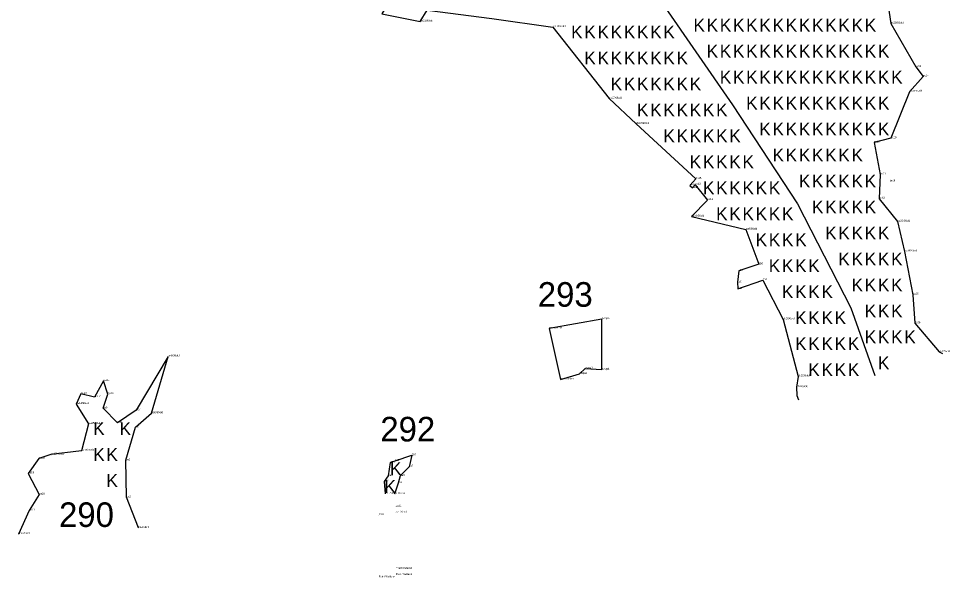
# Model space of a CAD drawing. Extents: x 2072529 to 2268812, y 436423 to 470008.
# Drawn here: x 2250300 to 2252772, y 437368 to 438853 of the extents above; entities that cross this region are included whole.
import ezdxf

# ---------------------------------------------------------------- set-up
doc = ezdxf.new("R2010")
doc.units = 0
for name, color, linetype in [('Old_Level_10', 7, 'Continuous'), ('Old_Level_20', 7, 'Continuous'), ('Old_Level_52', 7, 'Continuous'), ('Old_Level_55', 7, 'Continuous'), ('Old_Level_60', 7, 'Continuous'), ('Old_Level_62', 7, 'Continuous')]:
    doc.layers.add(name, color=color, linetype=linetype)

msp = doc.modelspace()

# ---------------------------------------------------------------- linework, layer by layer
at = {"layer": 'Old_Level_10'}
for p, q in [((2252009.775, 438893.449), (2252195.923, 438623.668)), ((2252195.923, 438623.668), (2252369.234, 438360.311)), ((2252369.234, 438360.311), (2252510.449, 438084.108)), ((2252510.449, 438084.108), (2252574.638, 437904.254))]:
    msp.add_line(p, q, dxfattribs=at)
msp.add_lwpolyline([(2251739.019, 437894.057), (2251789.687, 437908.798), (2251805.058, 437923.355), (2251849.076, 437920.135), (2251849.191, 438054.202), (2251709.629, 438029.479), (2251739.019, 437894.057)], dxfattribs=at)
at = {"layer": 'Old_Level_20'}
for p, q in [((2251366.822, 438844.78), (2251366.822, 438844.78)), ((2252617.059, 438839.416), (2252617.059, 438839.416)), ((2251718.819, 438830.133), (2251718.819, 438830.133)), ((2252682.756, 438724.15), (2252682.756, 438724.15)), ((2252702.337, 438698.781), (2252702.337, 438698.781)), ((2251868.445, 438639.973), (2251868.445, 438639.973)), ((2252666.604, 438658.157), (2252666.604, 438658.157)), ((2251940.741, 438572.887), (2251940.741, 438572.887)), ((2252572.116, 438523.425), (2252572.116, 438523.425)), ((2252617.067, 438534.575), (2252617.067, 438534.575)), ((2252098.489, 438426.718), (2252098.489, 438426.718)), ((2252588.626, 438438.611), (2252588.626, 438438.611)), ((2252614.962, 438420.413), (2252614.962, 438420.413)), ((2252083.026, 438409.31), (2252083.026, 438409.31)), ((2252090.254, 438402.804), (2252090.254, 438402.804)), ((2252096.843, 438411.378), (2252096.843, 438411.378)), ((2252129.608, 438370.679), (2252129.608, 438370.679)), ((2252585.902, 438374.204), (2252585.902, 438374.204)), ((2252087.239, 438326.638), (2252087.239, 438326.638)), ((2252231.674, 438292.269), (2252231.674, 438292.269)), ((2252634.629, 438313.221), (2252634.629, 438313.221)), ((2252652.916, 438234.163), (2252652.916, 438234.163)), ((2252265.763, 438199.96), (2252265.763, 438199.96)), ((2252213.023, 438182.133), (2252213.023, 438182.133)), ((2252209.119, 438152.048), (2252209.119, 438152.048)), ((2252276.43, 438157.855), (2252276.43, 438157.855)), ((2252210.196, 438134.316), (2252210.196, 438134.316)), ((2252675.403, 438119.227), (2252675.403, 438119.227)), ((2251849.191, 438054.202), (2251849.191, 438054.202)), ((2252330.724, 438053.701), (2252330.724, 438053.701)), ((2252680.549, 438043.335), (2252680.549, 438043.335)), ((2251709.629, 438029.479), (2251709.629, 438029.479)), ((2250696.964, 437955.41), (2250696.964, 437955.41)), ((2252745.583, 437967.012), (2252745.583, 437967.012)), ((2251805.058, 437923.355), (2251805.058, 437923.355)), ((2251849.076, 437920.135), (2251849.076, 437920.135)), ((2251789.687, 437908.798), (2251789.687, 437908.798)), ((2252370.675, 437902.256), (2252370.675, 437902.256)), ((2250525.719, 437889.973), (2250525.719, 437889.973)), ((2251739.019, 437894.057), (2251739.019, 437894.057)), ((2252366.636, 437873.552), (2252366.636, 437873.552)), ((2250465.038, 437855.514), (2250465.038, 437855.514)), ((2250501.969, 437847.269), (2250501.969, 437847.269)), ((2250537.012, 437854.96), (2250537.012, 437854.96)), ((2250452.829, 437828.757), (2250452.829, 437828.757)), ((2250524.177, 437817.337), (2250524.177, 437817.337)), ((2250611.988, 437812.401), (2250611.988, 437812.401)), ((2250653.197, 437804.291), (2250653.197, 437804.291)), ((2250485.912, 437775.713), (2250485.912, 437775.713)), ((2250562.617, 437779.2), (2250562.617, 437779.2)), ((2250610.143, 437767.229), (2250610.143, 437767.229)), ((2250466.867, 437704.451), (2250466.867, 437704.451)), ((2250354.116, 437683.813), (2250354.116, 437683.813)), ((2250385.955, 437694.223), (2250385.955, 437694.223)), ((2250585.02, 437679.174), (2250585.02, 437679.174)), ((2251287.405, 437673.349), (2251287.405, 437673.349)), ((2251299.79, 437677.728), (2251299.79, 437677.728)), ((2251344.17, 437692.721), (2251344.17, 437692.721)), ((2251336.971, 437662.251), (2251336.971, 437662.251)), ((2250325.657, 437644.544), (2250325.657, 437644.544)), ((2251271.614, 437623.095), (2251271.614, 437623.095)), ((2251282.305, 437637.555), (2251282.305, 437637.555)), ((2251313.853, 437637.655), (2251313.853, 437637.655)), ((2251307.811, 437618.563), (2251307.811, 437618.563)), ((2250354.188, 437588.248), (2250354.188, 437588.248)), ((2250586.417, 437580.895), (2250586.417, 437580.895)), ((2251274.586, 437590.445), (2251274.586, 437590.445)), ((2251298.576, 437589.587), (2251298.576, 437589.587)), ((2251301.541, 437556.181), (2251301.541, 437556.181)), ((2250327.585, 437546.154), (2250327.585, 437546.154)), ((2251256.501, 437533.612), (2251256.501, 437533.612)), ((2251302.043, 437540.012), (2251302.043, 437540.012)), ((2250618.387, 437499.578), (2250618.387, 437499.578)), ((2250299.983, 437483.136), (2250299.983, 437483.136))]:
    msp.add_line(p, q, dxfattribs=at)
at = {"layer": 'Old_Level_52'}
for points in [[(2251148.935, 439610.487), (2251261.982, 439510.927), (2251353.722, 439431.669), (2251408.061, 439276.459), (2251418.503, 439100.243), (2251356.472, 439015.142), (2251265.142, 438865.119), (2251366.822, 438844.78), (2251385.465, 438875.42), (2251556.913, 438853.097), (2251718.819, 438830.133), (2251868.445, 438639.973), (2251940.741, 438572.887), (2252098.489, 438426.718), (2252083.026, 438409.31), (2252090.254, 438402.804), (2252096.843, 438411.378), (2252129.608, 438370.679)], [(2252602.405, 438934.419), (2252617.059, 438839.416), (2252682.756, 438724.15), (2252702.337, 438698.781), (2252666.604, 438658.157), (2252617.067, 438534.575), (2252572.116, 438523.425), (2252588.626, 438438.611), (2252585.902, 438374.204), (2252634.629, 438313.221), (2252652.916, 438234.163), (2252675.403, 438119.227), (2252680.549, 438043.335), (2252745.583, 437967.012), (2252754.416, 437962.787)], [(2252129.608, 438370.679), (2252087.239, 438326.638), (2252231.674, 438292.269), (2252265.763, 438199.96), (2252213.023, 438182.133), (2252209.119, 438152.048), (2252210.196, 438134.316), (2252276.43, 438157.855), (2252330.724, 438053.701), (2252370.675, 437902.256), (2252366.636, 437873.552), (2252367.263, 437851.267), (2252371.205, 437840.036)], [(2250618.387, 437499.578), (2250586.417, 437580.895), (2250585.02, 437679.174), (2250610.143, 437767.229), (2250653.197, 437804.291), (2250696.964, 437955.41), (2250611.988, 437812.401), (2250562.617, 437779.2), (2250524.177, 437817.337), (2250537.012, 437854.96), (2250525.719, 437889.973), (2250501.969, 437847.269), (2250465.038, 437855.514), (2250452.829, 437828.757), (2250485.912, 437775.713), (2250466.867, 437704.451), (2250385.955, 437694.223), (2250354.116, 437683.813), (2250325.657, 437644.544), (2250354.188, 437588.248), (2250327.585, 437546.154), (2250299.983, 437483.136)], [(2251274.586, 437590.445), (2251271.614, 437623.095), (2251282.305, 437637.555), (2251287.405, 437673.349), (2251299.79, 437677.728), (2251344.17, 437692.721), (2251336.971, 437662.251), (2251313.853, 437637.655), (2251307.811, 437618.563), (2251298.576, 437589.587)]]:
    msp.add_lwpolyline(points, dxfattribs=at)

# ---------------------------------------------------------------- texts
at = {"layer": 'Old_Level_55'}
for p in [(2252092.495, 438818.088), (2252127.495, 438818.088), (2252162.495, 438818.088), (2252197.495, 438818.088), (2252232.495, 438818.088), (2252267.495, 438818.088), (2252302.495, 438818.088), (2252337.495, 438818.088), (2252372.495, 438818.088), (2252407.495, 438818.088), (2252442.495, 438818.088), (2252477.495, 438818.088), (2252512.495, 438818.088), (2252547.495, 438818.088), (2251767.66, 438800.046), (2251802.66, 438800.046), (2251837.66, 438800.046), (2251872.66, 438800.046), (2251907.66, 438800.046), (2251942.66, 438800.046), (2251977.66, 438800.046), (2252012.66, 438800.046), (2251802.66, 438731.046), (2251837.66, 438731.046), (2251872.66, 438731.046), (2251907.66, 438731.046), (2251942.66, 438731.046), (2251977.66, 438731.046), (2252012.66, 438731.046), (2252047.66, 438731.046), (2252127.495, 438749.088), (2252162.495, 438749.088), (2252197.495, 438749.088), (2252232.495, 438749.088), (2252267.495, 438749.088), (2252302.495, 438749.088), (2252337.495, 438749.088), (2252372.495, 438749.088), (2252407.495, 438749.088), (2252442.495, 438749.088), (2252477.495, 438749.088), (2252512.495, 438749.088), (2252547.495, 438749.088), (2252582.495, 438749.088), (2252162.495, 438680.088), (2252197.495, 438680.088), (2252232.495, 438680.088), (2252267.495, 438680.088), (2252302.495, 438680.088), (2252337.495, 438680.088), (2252372.495, 438680.088), (2252407.495, 438680.088), (2252442.495, 438680.088), (2252477.495, 438680.088), (2252512.495, 438680.088), (2252547.495, 438680.088), (2252582.495, 438680.088), (2252617.495, 438680.088), (2251872.66, 438662.046), (2251907.66, 438662.046), (2251942.66, 438662.046), (2251977.66, 438662.046), (2252012.66, 438662.046), (2252047.66, 438662.046), (2252082.66, 438662.046), (2252232.495, 438611.088), (2252267.495, 438611.088), (2252302.495, 438611.088), (2252337.495, 438611.088), (2252372.495, 438611.088), (2252407.495, 438611.088), (2252442.495, 438611.088), (2252477.495, 438611.088), (2252512.495, 438611.088), (2252547.495, 438611.088), (2252582.495, 438611.088), (2251942.66, 438593.046), (2251977.66, 438593.046), (2252012.66, 438593.046), (2252047.66, 438593.046), (2252082.66, 438593.046), (2252117.66, 438593.046), (2252152.66, 438593.046), (2252267.495, 438542.088), (2252302.495, 438542.088), (2252337.495, 438542.088), (2252372.495, 438542.088), (2252407.495, 438542.088), (2252442.495, 438542.088), (2252477.495, 438542.088), (2252512.495, 438542.088), (2252547.495, 438542.088), (2252582.495, 438542.088), (2252012.66, 438524.046), (2252047.66, 438524.046), (2252082.66, 438524.046), (2252117.66, 438524.046), (2252152.66, 438524.046), (2252187.66, 438524.046), (2252082.66, 438455.046), (2252117.66, 438455.046), (2252152.66, 438455.046), (2252187.66, 438455.046), (2252222.66, 438455.046), (2252302.495, 438473.088), (2252337.495, 438473.088), (2252372.495, 438473.088), (2252407.495, 438473.088), (2252442.495, 438473.088), (2252477.495, 438473.088), (2252512.495, 438473.088), (2252117.66, 438386.046), (2252152.66, 438386.046), (2252187.66, 438386.046), (2252222.66, 438386.046), (2252257.66, 438386.046), (2252292.66, 438386.046), (2252372.495, 438404.088), (2252407.495, 438404.088), (2252442.495, 438404.088), (2252477.495, 438404.088), (2252512.495, 438404.088), (2252547.495, 438404.088), (2252407.495, 438335.088), (2252442.495, 438335.088), (2252477.495, 438335.088), (2252512.495, 438335.088), (2252547.495, 438335.088), (2252152.66, 438317.046), (2252187.66, 438317.046), (2252222.66, 438317.046), (2252257.66, 438317.046), (2252292.66, 438317.046), (2252327.66, 438317.046), (2252442.495, 438266.088), (2252477.495, 438266.088), (2252512.495, 438266.088), (2252547.495, 438266.088), (2252582.495, 438266.088), (2252257.66, 438248.046), (2252292.66, 438248.046), (2252327.66, 438248.046), (2252362.66, 438248.046), (2252477.495, 438197.088), (2252512.495, 438197.088), (2252547.495, 438197.088), (2252582.495, 438197.088), (2252617.495, 438197.088), (2252292.66, 438179.046), (2252327.66, 438179.046), (2252362.66, 438179.046), (2252397.66, 438179.046), (2252327.66, 438110.046), (2252362.66, 438110.046), (2252397.66, 438110.046), (2252432.66, 438110.046), (2252512.495, 438128.088), (2252547.495, 438128.088), (2252582.495, 438128.088), (2252617.495, 438128.088), (2252547.495, 438059.088), (2252582.495, 438059.088), (2252617.495, 438059.088), (2252362.66, 438041.046), (2252397.66, 438041.046), (2252432.66, 438041.046), (2252467.66, 438041.046), (2252547.495, 437990.088), (2252582.495, 437990.088), (2252617.495, 437990.088), (2252652.495, 437990.088), (2252362.66, 437972.046), (2252397.66, 437972.046), (2252432.66, 437972.046), (2252467.66, 437972.046), (2252502.66, 437972.046), (2252582.495, 437921.088), (2252397.66, 437903.046), (2252432.66, 437903.046), (2252467.66, 437903.046), (2252502.66, 437903.046), (2250498.098, 437746.518), (2250568.098, 437746.518), (2250498.098, 437677.518), (2250533.098, 437677.518), (2251286.449, 437640.043), (2250533.098, 437608.518), (2251271.455, 437592.56)]:
    msp.add_text('K', height=34, dxfattribs=at).set_placement(p)
at = {"layer": 'Old_Level_60'}
for s, p in [('zb21/96old', (2251366.822, 438844.78)), ('zb18/96old', (2251718.819, 438830.133)), ('zc25/96old', (2252617.059, 438839.416)), ('zc26', (2252682.756, 438724.15)), ('zc27', (2252702.337, 438698.781)), ('zc28/96old', (2252666.604, 438658.157)), ('zb17/96old', (2251868.445, 438639.973)), ('zb16/96old', (2251940.741, 438572.887)), ('zc29', (2252617.067, 438534.575)), ('zc30', (2252572.116, 438523.425)), ('zc31', (2252588.626, 438438.611)), ('zb14', (2252083.026, 438409.31)), ('zb12', (2252096.843, 438411.378)), ('zb15', (2252098.489, 438426.718)), ('arch', (2252614.962, 438420.413)), ('zb13', (2252090.254, 438402.804)), ('zb11', (2252129.608, 438370.679)), ('zc32', (2252585.902, 438374.204)), ('zb10/96old', (2252087.239, 438326.638)), ('zc33/96old', (2252634.629, 438313.221)), ('za9/96old', (2252231.674, 438292.269)), ('zc34/96old', (2252652.916, 438234.163)), ('zb8', (2252265.763, 438199.96)), ('zb7', (2252213.023, 438182.133)), ('zb6', (2252209.119, 438152.048)), ('zb4', (2252276.43, 438157.855)), ('zb5', (2252210.196, 438134.316)), ('zc35', (2252675.403, 438119.227)), ('swqa5', (2251849.191, 438054.202)), ('zb3/96old', (2252330.724, 438053.701)), ('zc36', (2252680.549, 438043.335)), ('swqa6/end', (2251709.629, 438029.479)), ('zc37/end', (2252745.583, 437967.012)), ('pa6/96old', (2250696.964, 437955.41)), ('swqa3', (2251805.058, 437923.355)), ('swqa4', (2251849.076, 437920.135)), ('pa11', (2250525.719, 437889.973)), ('swqa1/start', (2251739.019, 437894.057)), ('swqa2', (2251789.687, 437908.798)), ('zb2/96old', (2252370.675, 437902.256)), ('zb1/96old', (2252366.636, 437873.552)), ('pa13', (2250465.038, 437855.514)), ('pa12', (2250501.969, 437847.269)), ('pa10', (2250537.012, 437854.96)), ('pa14/96old', (2250452.829, 437828.757)), ('pa9', (2250524.177, 437817.337)), ('pa7', (2250611.988, 437812.401)), ('pa5/96old', (2250653.197, 437804.291)), ('pa15/96old', (2250485.912, 437775.713)), ('pa8', (2250562.617, 437779.2)), ('pa4', (2250610.143, 437767.229)), ('pa17/96old', (2250385.955, 437694.223)), ('pa16/96old', (2250466.867, 437704.451)), ('za7', (2251344.17, 437692.721)), ('pa18', (2250354.116, 437683.813)), ('pa3', (2250585.02, 437679.174)), ('za4', (2251287.405, 437673.349)), ('za5', (2251299.79, 437677.728)), ('pa19', (2250325.657, 437644.544)), ('za7', (2251336.971, 437662.251)), ('za2', (2251271.614, 437623.095)), ('za3', (2251282.305, 437637.555)), ('za9', (2251307.811, 437618.563)), ('za8', (2251313.853, 437637.655)), ('pa20', (2250354.188, 437588.248)), ('pa2', (2250586.417, 437580.895)), ('za1/start', (2251274.586, 437590.445)), ('za10/end', (2251298.576, 437589.587)), ('pa21', (2250327.585, 437546.154)), ('za11', (2251301.541, 437556.181)), ('za1a', (2251256.501, 437533.612)), ('za12/end', (2251302.043, 437540.012)), ('pa1/start', (2250618.387, 437499.578)), ('pa22/end', (2250299.983, 437483.136)), ('Point Wetland', (2251301.541, 437390.84)), ('Point Wetland', (2251302.043, 437374.671)), ('Point Wetland', (2251256.501, 437368.271))]:
    msp.add_text(s, height=5, dxfattribs=at).set_placement(p)
at = {"layer": 'Old_Level_62'}
for s, p in [('293', (2251679.148, 438087.172)), ('292', (2251260.754, 437729.321)), ('290', (2250407.374, 437502.133))]:
    msp.add_text(s, height=65.34, dxfattribs=at).set_placement(p)

doc.saveas('drawing.dxf')
